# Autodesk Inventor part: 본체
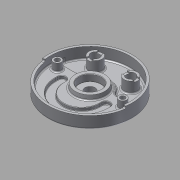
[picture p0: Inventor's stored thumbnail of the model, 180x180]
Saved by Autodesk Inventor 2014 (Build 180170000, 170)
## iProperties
Created: 2015-06
Part Number: 본체
Material: 알루미늄 6061
Document SubType Name: Modeling
Designer: MYHOME
Density: 2.71 g/cm^3
Appearance: 알루미늄 - 평지
Mass: 1076.53 g
Surface Area: 1039.73 cm^2
Volume: 397.244 cm^3
Author: MYHOME
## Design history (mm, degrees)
sketch "스케치1"
  geometry: C1 r 95 at (0, 0); 1 further point
  constraints: 1 centre point, 1 coincident
  dimensions: "d0" = 190 diameter of C1
extrude "돌출1" new body sketch "스케치1" distance "d1" = 32; taper "d2" = 0 deg
sketch "스케치2"
  geometry: C1 r 95 at (0, 0) reference; C2 r 90 at (0, 0)
  constraints: 1 centre point, 1 coincident
  dimensions: "d3" = 180 diameter of C2
extrude "돌출2" cut sketch "스케치2" distance "d4" = 18; taper "d5" = 0 deg
sketch "스케치3"
  geometry: C1 r 90 at (0, 0) reference; C2 r 35 at (0, 0)
  constraints: 1 centre point, 1 coincident
  dimensions: "d6" = 70 diameter of C2
extrude "돌출3" join sketch "스케치3" distance "d7" = 10; taper "d8" = -10 deg
sketch "스케치4"
  geometry: C1 r 95 at (0, 0) reference; C2 r 26 at (0, 0)
  constraints: 1 centre point, 1 coincident
  dimensions: "d9" = 52 diameter of C2
extrude "돌출4" join sketch "스케치4" distance "d10" = 12; taper "d11" = -15 deg
sketch "스케치5"
  geometry: C1 r 33.237 at (0, 0) reference; C2 r 25 at (0, 0)
  constraints: 1 centre point, 1 coincident
  dimensions: "d12" = 50 diameter of C2
extrude "돌출5" cut sketch "스케치5" distance "d13" = 15; taper "d14" = 0 deg
sketch "스케치6"
  geometry: C1 r 22.785 at (0, 0) reference; C2 r 11.5 at (0, 0)
  constraints: 1 centre point, 1 coincident
  dimensions: "d15" = 23 diameter of C2
extrude "돌출6" cut sketch "스케치6" stored distance "d16" = 15; taper "d17" = 0 deg
sketch "스케치7"
  geometry: L1 (-59, -19)-(-41, -19); L2 (41, -19)-(59, -19); L3 (-50, -24)-(-50, -14); L4 (-59, -14)-(-59, -19); L5 (-41, -14)-(-41, -19); L6 (41, -14)-(41, -19); L7 (59, -14)-(59, -19); C1 r 35 at (0, 0) reference; A1 r 41 centre (0, -19) between (-41, -19) and (41, -19); A2 r 59 centre (0, -19) between (-59, -19) and (59, -19); A3 r 9 centre (-50, -14) between (-41, -14) and (-59, -14); A4 r 9 centre (50, -14) between (59, -14) and (41, -14); 1 further point
  constraints: 16 end point, 8 point on circle, 5 tangent, 4 centre point, 2 midpoint, 1 coincident, 1 collinear, 1 horizontal, 1 parallel, 1 perpendicular, 1 vertical alignment
  dimensions: "d18" = 19 distance of A1.centre C1.centre; "d19" = 41 radius of A1; "d20" = 59 radius of A2; "d21" = 18 distance of L2.start L2.end; "d22" = 18 distance of L1.start L1.end; "d23" = 5 distance of point (-50, -19) L3.end; "d25" = 9 radius of A4; "d26" = 5 vertical distance of A1.centre A4.centre
extrude "돌출7" cut sketch "스케치7" distance "d27" = 7; taper "d28" = 0 deg
sketch "스케치9"
  geometry: L1 (-59, -19)-(-59, -14) reference; L2 (-88.566, 16)-(-38.833, 16); L3 (38.833, 16)-(88.566, 16); A1 r 90 centre (0, 0) between (-88.566, 16) and (88.566, 16) reference; A2 r 42 centre (0, 0) between (-38.833, 16) and (38.833, 16)
  constraints: 4 end point, 4 point on circle, 2 collinear, 1 centre point, 1 coincident, 1 perpendicular
  dimensions: "d33" = 84 diameter of A2; "d34" = 16 distance from line of A2.centre L2
extrude "돌출9" cut sketch "스케치9" distance "d35" = 7; taper "d36" = 0 deg
fillet "모깎기2" dims "d37" = 10
sketch "스케치10"
  geometry: C1 r 15 at (-40, 52); C2 r 15 at (40, 52); A1 r 90 centre (0, 0) between (85.114, 29.25) and (-85.114, 29.25) reference
  constraints: 2 centre point, 1 horizontal alignment
  dimensions: "d38" = 30 diameter of C1; "d39" = 30 diameter of C2; "d40" = 80 distance of C2.centre C1.centre; "d41" = 40 horizontal distance of A1.centre C2.centre; "d42" = 52 vertical distance of A1.centre C1.centre
extrude "돌출10" join sketch "스케치10" distance "d43" = 25; taper "d44" = 0 deg
sketch "스케치11"
  geometry: C1 r 15 at (0, 0) reference; C2 r 10 at (0, 0); C3 r 15 at (-80, 0) reference; C4 r 10 at (-80, 0); 1 further point
  constraints: 2 centre point, 2 coincident
  dimensions: "d45" = 20 diameter of C2; "d46" = 20 diameter of C4
extrude "돌출11" cut sketch "스케치11" stored distance "d47" = 25; taper "d48" = 0 deg
sketch "스케치12"
  geometry: L1 (-6, 13.748)-(-6, -13.748); L2 (6, 13.748)-(6, -13.748); L3 (66.252, 6)-(93.748, 6); L4 (66.252, -6)-(93.748, -6); C1 r 10 at (0, 0) reference; C2 r 10 at (80, 0) reference; A1 r 15 centre (0, 0) between (-6, 13.748) and (-6, -13.748) reference; A2 r 15 centre (80, 0) between (66.252, 6) and (93.748, 6) reference; 1 further point
  constraints: 8 end point, 8 point on circle, 2 parallel, 1 perpendicular, 1 vertical
  dimensions: "d49" = 12 distance between parallel lines of L2 L1; "d50" = 12 distance between parallel lines of L4 L3; "d51" = 6 distance from line of L2 C1.centre; "d52" = 6 distance from line of C2.centre L3
extrude "돌출12" cut sketch "스케치12" distance "d53" = 3; taper "d54" = 0 deg
sketch "스케치13"
  geometry: C1 r 26 at (0, 0) reference; C2 r 9 at (-74, 0); C3 r 9 at (74, 0)
  constraints: 2 centre point, 2 horizontal alignment
  dimensions: "d55" = 18 diameter of C2; "d56" = 18 diameter of C3; "d57" = 148 distance of C3.centre C2.centre; "d58" = 74 distance of C2.centre C1.centre
extrude "돌출13" cut sketch "스케치13" distance "d59" = 11; taper "d60" = 0 deg
sketch "스케치14"
  geometry: C1 r 9 at (-74, 0); C2 r 9 at (74, 0); A1 r 90 centre (0, 0) between (-85.114, 29.25) and (85.114, 29.25) reference
  constraints: 2 centre point, 2 horizontal alignment
  dimensions: "d61" = 18 diameter of C1; "d62" = 18 diameter of C2; "d63" = 148 distance of C2.centre C1.centre; "d64" = 74 distance of C1.centre A1.centre
extrude "돌출14" join sketch "스케치14" distance "d65" = 18; taper "d66" = 0 deg
sketch "스케치15"
  geometry: C1 r 9 at (0, 0) reference; C2 r 9 at (148, 0) reference; C3 r 5.5 at (0, 0); C4 r 5.5 at (148, 0); 1 further point
  constraints: 2 centre point, 2 coincident
  dimensions: "d67" = 11 diameter of C3; "d68" = 11 diameter of C4
extrude "돌출15" cut sketch "스케치15" stored distance "d69" = 18; taper "d70" = 0 deg
sketch "스케치16"
  geometry: L1 (0, 0)-(-94.075, -13.221); L2 (0, 0)-(94.075, -13.221); L3 (0, 0)-(-95, 0); L4 (0, 0)-(95, 0); A1 r 90 centre (0, 0) between (-89.124, -12.526) and (89.124, -12.526) reference; A2 r 95 centre (0, 0) between (-94.075, -13.221) and (94.075, -13.221) reference
  constraints: 8 end point, 6 point on circle, 2 point on line, 1 collinear, 1 horizontal
  dimensions: "d71" = 8 deg angle of L1 L3; "d72" = 8 deg angle of L2 L4
extrude "돌출16" cut sketch "스케치16" distance "d73" = 5; taper "d74" = 0 deg
sketch "스케치17"
  geometry: C1 r 95 at (0, 0) reference; C2 r 68 at (0, 0)
  constraints: 1 centre point, 1 coincident, 1 other
  dimensions: "d75" = 136 diameter of C2
feature "엠보싱1" sketch "스케치17" dims "d76" = 0.5, "d77" = 0
fillet "모깎기3" dims "d78" = 0.3
chamfer "모따기1" distance "d79" = 1; stored, may be unused: second distance "d80" = 2, angle "d81" = 45 deg
fillet "모깎기4" dims "d82" = 3
fillet "모깎기5" dims "d83" = 1
fillet "모깎기6" dims "d84" = 3
fillet "모깎기7" dims "d85" = 3
fillet "모깎기8" dims "d86" = 3
fillet "모깎기9" dims "d87" = 3
chamfer "모따기2" distance "d88" = 1; stored, may be unused: second distance "d89" = 2, angle "d90" = 45 deg
fillet "모깎기10" dims "d91" = 3
node "솔리드1"
node "투영된 루프1"
node "투영된 루프2"
